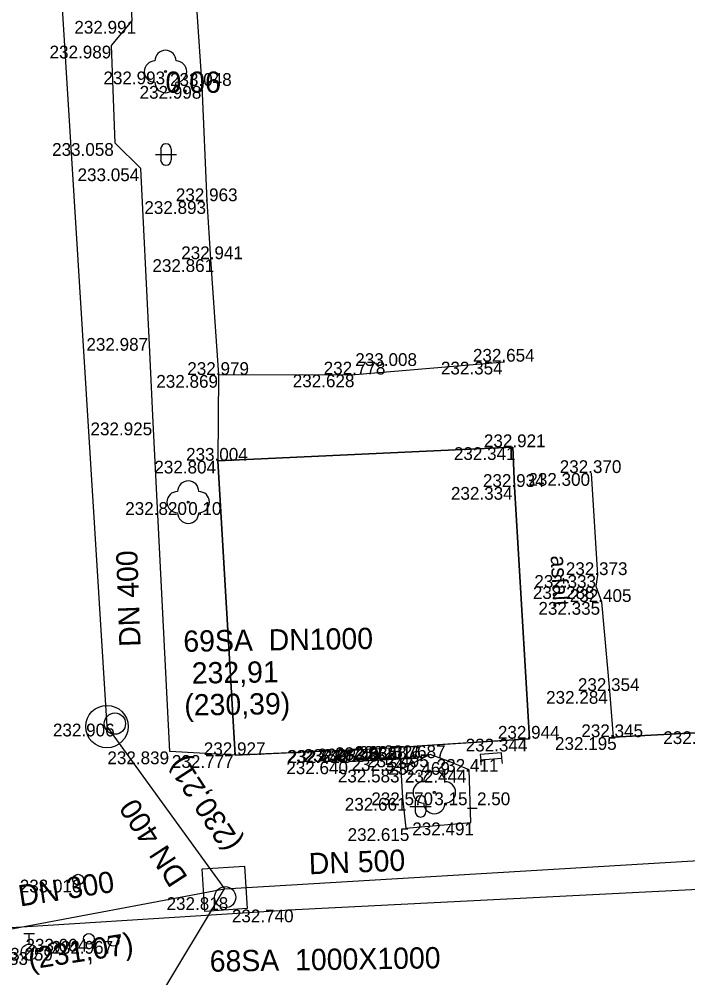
# Model space of a CAD drawing. Extents: x -599516 to -599132, y -1163668 to -1163119.
# Drawn here: x -599493.05 to -599477.33, y -1163377.96 to -1163355.43 of the extents above; entities that cross this region are included whole.
import ezdxf

# ---------------------------------------------------------------- set-up
doc = ezdxf.new("R2010")
doc.units = 0
for name, color, linetype in [('Bod-oznac1', 7, 'Continuous'), ('Bod-oznac2', 7, 'Continuous'), ('Bod-oznac3', 7, 'Continuous'), ('Bod-vyska1', 7, 'Continuous'), ('Bod-vyska2', 7, 'Continuous'), ('Bod-vyska3', 7, 'Continuous'), ('Z_cela-hrobu-dolni-linie', 7, 'Continuous'), ('Z_cela-hrobu-horni-linie', 7, 'Continuous'), ('Z_chodnik', 7, 'Continuous'), ('Z_kanalizace-destova', 7, 'Continuous'), ('Z_kanalizace-znacky-sachta', 7, 'Continuous'), ('Z_komunikace', 7, 'Continuous'), ('Z_komunikace-osa', 7, 'Continuous'), ('Z_kultury-znacky', 7, 'Continuous'), ('Z_nove-stromy-prumer-kmene', 7, 'Continuous'), ('Z_obvod-kmene-spodek-ve-vysce1_2m', 7, 'Continuous'), ('Z_podzemni-obrys-sachty', 7, 'Continuous'), ('Z_popis-budov-povrchu', 7, 'Continuous'), ('Z_stromy-kere', 7, 'Continuous'), ('Z_stromy-nove-vysazene', 7, 'Continuous'), ('Z_voda-znacky-hydrant', 7, 'Continuous'), ('Z_voda-znacky-soupe', 7, 'Continuous'), ('Z_znacky-ostatni-lavicka', 7, 'Continuous'), ('Z_zpevnene-plochy', 7, 'Continuous')]:
    doc.layers.add(name, color=color, linetype=linetype)

msp = doc.modelspace()

# ---------------------------------------------------------------- linework, layer by layer
at = {"layer": 'Bod-oznac1'}
for p, q in [((-599490.396, -1163355.473), (-599490.396, -1163355.473)), ((-599490.875, -1163356.055), (-599490.875, -1163356.055)), ((-599489.609, -1163356.663), (-599489.609, -1163356.663)), ((-599488.758, -1163357.001), (-599488.758, -1163357.001)), ((-599490.794, -1163358.344), (-599490.794, -1163358.344)), ((-599490.185, -1163358.938), (-599490.185, -1163358.938)), ((-599488.636, -1163359.709), (-599488.636, -1163359.709)), ((-599488.55, -1163361.072), (-599488.55, -1163361.072)), ((-599489.996, -1163362.923), (-599489.996, -1163362.923)), ((-599481.64, -1163363.48), (-599481.64, -1163363.48)), ((-599488.366, -1163363.792), (-599488.366, -1163363.792)), ((-599485.147, -1163363.781), (-599485.147, -1163363.781)), ((-599489.902, -1163364.909), (-599489.902, -1163364.909)), ((-599481.44, -1163365.489), (-599481.44, -1163365.489)), ((-599488.38, -1163365.807), (-599488.38, -1163365.807)), ((-599479.6, -1163366.096), (-599479.6, -1163366.096)), ((-599481.405, -1163366.423), (-599481.405, -1163366.423)), ((-599489.075, -1163366.78), (-599489.075, -1163366.78)), ((-599479.455, -1163368.493), (-599479.455, -1163368.493)), ((-599479.49, -1163368.755), (-599479.49, -1163368.755)), ((-599479.359, -1163369.125), (-599479.359, -1163369.125)), ((-599479.168, -1163371.217), (-599479.168, -1163371.217)), ((-599490.798, -1163371.984), (-599490.798, -1163371.984)), ((-599481.048, -1163372.338), (-599481.048, -1163372.338)), ((-599479.086, -1163372.301), (-599479.086, -1163372.301)), ((-599484.881, -1163372.584), (-599484.881, -1163372.584)), ((-599484.881, -1163372.585), (-599484.881, -1163372.585)), ((-599484.152, -1163372.54), (-599484.152, -1163372.54)), ((-599484.152, -1163372.542), (-599484.152, -1163372.542)), ((-599483.693, -1163372.512), (-599483.693, -1163372.512)), ((-599483.691, -1163372.512), (-599483.691, -1163372.512)), ((-599489.505, -1163372.637), (-599489.505, -1163372.637)), ((-599487.972, -1163372.723), (-599487.972, -1163372.723)), ((-599485.264, -1163372.607), (-599485.264, -1163372.607)), ((-599485.263, -1163372.607), (-599485.263, -1163372.607)), ((-599483.74, -1163372.794), (-599483.74, -1163372.794)), ((-599483.388, -1163372.709), (-599483.388, -1163372.709)), ((-599485.289, -1163372.871), (-599485.289, -1163372.871)), ((-599482.904, -1163372.886), (-599482.904, -1163372.886)), ((-599481.948, -1163372.815), (-599481.948, -1163372.815)), ((-599484.074, -1163373.065), (-599484.074, -1163373.065)), ((-599482.466, -1163373.068), (-599482.466, -1163373.068)), ((-599483.289, -1163373.6), (-599483.289, -1163373.6)), ((-599484.039, -1163373.729), (-599484.039, -1163373.729)), ((-599482.429, -1163374.306), (-599482.429, -1163374.306)), ((-599483.961, -1163374.441), (-599483.961, -1163374.441)), ((-599491.661, -1163375.649), (-599491.661, -1163375.649)), ((-599488.206, -1163376.062), (-599488.206, -1163376.062)), ((-599486.555, -1163376.352), (-599486.555, -1163376.352)), ((-599491.411, -1163377.04), (-599491.411, -1163377.04)), ((-599490.831, -1163377.09), (-599490.831, -1163377.09)), ((-599492.239, -1163377.252), (-599492.239, -1163377.252)), ((-599492.813, -1163377.352), (-599492.813, -1163377.352))]:
    msp.add_line(p, q, dxfattribs=at)
at = {"layer": 'Bod-oznac2'}
for p, q in [((-599488.758, -1163357.001), (-599488.758, -1163357.001)), ((-599488.636, -1163359.709), (-599488.636, -1163359.709)), ((-599488.55, -1163361.072), (-599488.55, -1163361.072)), ((-599481.64, -1163363.48), (-599481.64, -1163363.48)), ((-599488.366, -1163363.792), (-599488.366, -1163363.792)), ((-599485.147, -1163363.781), (-599485.147, -1163363.781)), ((-599481.44, -1163365.489), (-599481.44, -1163365.489)), ((-599488.38, -1163365.807), (-599488.38, -1163365.807)), ((-599479.6, -1163366.096), (-599479.6, -1163366.096)), ((-599481.405, -1163366.423), (-599481.405, -1163366.423)), ((-599479.455, -1163368.493), (-599479.455, -1163368.493)), ((-599479.359, -1163369.125), (-599479.359, -1163369.125)), ((-599479.168, -1163371.217), (-599479.168, -1163371.217)), ((-599481.048, -1163372.338), (-599481.048, -1163372.338)), ((-599479.086, -1163372.301), (-599479.086, -1163372.301)), ((-599487.972, -1163372.723), (-599487.972, -1163372.723)), ((-599483.74, -1163372.794), (-599483.74, -1163372.794)), ((-599485.289, -1163372.871), (-599485.289, -1163372.871))]:
    msp.add_line(p, q, dxfattribs=at)
at = {"layer": 'Bod-oznac3'}
msp.add_line((-599485.147, -1163363.781), (-599485.147, -1163363.781), dxfattribs=at)
at = {"layer": 'Z_cela-hrobu-dolni-linie'}
msp.add_line((-599487.972, -1163372.723), (-599488.38, -1163365.807), dxfattribs=at)
msp.add_lwpolyline([(-599489.004, -1163353.298), (-599488.758, -1163357.001), (-599488.636, -1163359.709), (-599488.55, -1163361.072), (-599488.366, -1163363.792)], dxfattribs=at)
at = {"layer": 'Z_cela-hrobu-horni-linie'}
msp.add_line((-599479.6, -1163366.096), (-599479.455, -1163368.493), dxfattribs=at)
for points in [[(-599489.004, -1163353.298), (-599488.758, -1163357.001), (-599488.636, -1163359.709), (-599488.55, -1163361.072), (-599488.366, -1163363.792), (-599485.147, -1163363.781), (-599485.147, -1163363.781), (-599481.64, -1163363.48)], [(-599484.152, -1163372.542), (-599484.152, -1163372.54), (-599481.048, -1163372.338), (-599481.405, -1163366.423), (-599481.44, -1163365.489), (-599488.38, -1163365.807)], [(-599488.38, -1163365.807), (-599487.972, -1163372.723), (-599484.881, -1163372.584), (-599484.881, -1163372.585), (-599484.152, -1163372.542)], [(-599479.086, -1163372.301), (-599476.413, -1163372.163), (-599476.413, -1163372.163), (-599473.687, -1163371.969), (-599473.687, -1163371.969), (-599471.002, -1163371.829), (-599471.002, -1163371.829), (-599468.212, -1163371.65), (-599468.212, -1163371.65), (-599466.846, -1163371.574), (-599466.846, -1163371.574), (-599461.29, -1163371.24), (-599461.384, -1163367.744)], [(-599479.359, -1163369.125), (-599479.168, -1163371.217), (-599479.086, -1163372.301)]]:
    msp.add_lwpolyline(points, dxfattribs=at)
at = {"layer": 'Z_chodnik'}
for points in [[(-599488.366, -1163363.792), (-599485.147, -1163363.781), (-599481.64, -1163363.48)], [(-599488.366, -1163363.792), (-599488.38, -1163365.807), (-599481.44, -1163365.489)]]:
    msp.add_lwpolyline(points, dxfattribs=at)
at = {"layer": 'Z_kanalizace-destova'}
for p, q in [((-599494.722, -1163312.287), (-599490.985, -1163372.054)), ((-599488.219, -1163375.862), (-599421.433, -1163371.876)), ((-599490.985, -1163372.054), (-599488.219, -1163375.862)), ((-599502.504, -1163378.542), (-599488.219, -1163375.862)), ((-599490.798, -1163380.14), (-599488.219, -1163375.862))]:
    msp.add_line(p, q, dxfattribs=at)
at = {"layer": 'Z_kanalizace-znacky-sachta'}
for centre in [(-599490.798, -1163371.984), (-599488.206, -1163376.062)]:
    msp.add_circle(centre, 0.25, dxfattribs=at)
at = {"layer": 'Z_komunikace'}
for points in [[(-599489.902, -1163364.909), (-599489.996, -1163362.923), (-599490.185, -1163358.938), (-599490.794, -1163358.344), (-599490.875, -1163356.055), (-599490.396, -1163355.473), (-599490.586, -1163351.474), (-599490.883, -1163347.19), (-599491.117, -1163346.799), (-599491.182, -1163345.761), (-599490.938, -1163344.776), (-599491.152, -1163341.79), (-599492.205, -1163340.898), (-599492.27, -1163339.868), (-599491.269, -1163338.743), (-599491.456, -1163334.806), (-599491.693, -1163331.006), (-599492.092, -1163330.613), (-599492.139, -1163328.983), (-599491.859, -1163328.546), (-599491.882, -1163327.381), (-599492.1, -1163323.823), (-599492.5, -1163319.448)], [(-599481.44, -1163365.489), (-599481.405, -1163366.423), (-599481.048, -1163372.338), (-599483.691, -1163372.512), (-599483.74, -1163372.794), (-599485.289, -1163372.871), (-599485.264, -1163372.607), (-599487.972, -1163372.723), (-599489.505, -1163372.637), (-599489.902, -1163364.909)], [(-599479.6, -1163366.096), (-599479.455, -1163368.493), (-599479.49, -1163368.755), (-599479.359, -1163369.125), (-599479.168, -1163371.217), (-599479.086, -1163372.301)], [(-599476.413, -1163372.163), (-599479.086, -1163372.301)], [(-599484.074, -1163373.065), (-599484.039, -1163373.729), (-599483.961, -1163374.441), (-599482.429, -1163374.306), (-599482.466, -1163373.068), (-599482.904, -1163372.886), (-599483.388, -1163372.709), (-599484.074, -1163373.065)]]:
    msp.add_lwpolyline(points, dxfattribs=at)
at = {"layer": 'Z_komunikace-osa'}
for points in [[(-599486.555, -1163376.352), (-599466.362, -1163375.334), (-599448.228, -1163374.387), (-599430.144, -1163373.279), (-599420.689, -1163372.612)], [(-599501.133, -1163377.406), (-599495.218, -1163376.901), (-599486.555, -1163376.352)]]:
    msp.add_lwpolyline(points, dxfattribs=at)
at = {"layer": 'Z_kultury-znacky'}
for p, q in [((-599489.847, -1163358.612), (-599489.347, -1163358.612)), ((-599489.722, -1163358.487), (-599489.722, -1163358.737)), ((-599489.472, -1163358.487), (-599489.472, -1163358.737)), ((-599483.861, -1163373.928), (-599483.361, -1163373.928)), ((-599483.736, -1163373.803), (-599483.736, -1163374.053)), ((-599483.486, -1163373.803), (-599483.486, -1163374.053))]:
    msp.add_line(p, q, dxfattribs=at)
for centre, start, end in [((-599489.598, -1163358.487), 0, 180), ((-599489.598, -1163358.737), 180, 0), ((-599483.611, -1163373.803), 0, 180), ((-599483.611, -1163374.053), 180, 0)]:
    msp.add_arc(centre, 0.125, start, end, dxfattribs=at)
at = {"layer": 'Z_podzemni-obrys-sachty'}
msp.add_line((-599488.684, -1163376.394), (-599488.75, -1163375.396), dxfattribs=at)
msp.add_lwpolyline([(-599488.75, -1163375.396), (-599487.754, -1163375.331), (-599487.688, -1163376.329), (-599488.684, -1163376.394)], dxfattribs=at)
msp.add_circle((-599490.985, -1163372.054), 0.5, dxfattribs=at)
at = {"layer": 'Z_stromy-kere'}
msp.add_circle((-599483.289, -1163373.6), 0.025, dxfattribs=at)
for centre, start, end in [((-599483.289, -1163373.35), 0, 180), ((-599483.539, -1163373.6), 90, 270), ((-599483.039, -1163373.6), 270, 90), ((-599483.289, -1163373.85), 180, 0)]:
    msp.add_arc(centre, 0.25, start, end, dxfattribs=at)
at = {"layer": 'Z_stromy-nove-vysazene'}
for centre in [(-599489.609, -1163356.663), (-599489.075, -1163366.78)]:
    msp.add_circle(centre, 0.025, dxfattribs=at)
for centre, start, end in [((-599489.609, -1163356.413), 0, 180), ((-599489.859, -1163356.663), 90, 270), ((-599489.359, -1163356.663), 270, 90), ((-599489.609, -1163356.913), 180, 0), ((-599489.075, -1163366.53), 0, 180), ((-599489.325, -1163366.78), 90, 270), ((-599488.825, -1163366.78), 270, 90), ((-599489.075, -1163367.03), 180, 0)]:
    msp.add_arc(centre, 0.25, start, end, dxfattribs=at)
at = {"layer": 'Z_voda-znacky-hydrant'}
for p, q in [((-599492.938, -1163376.914), (-599492.688, -1163376.914)), ((-599492.813, -1163377.164), (-599492.813, -1163376.914)), ((-599492.681, -1163377.22), (-599492.946, -1163377.485))]:
    msp.add_line(p, q, dxfattribs=at)
msp.add_circle((-599492.813, -1163377.352), 0.188, dxfattribs=at)
at = {"layer": 'Z_voda-znacky-soupe'}
for centre in [(-599491.661, -1163375.649), (-599491.411, -1163377.04), (-599490.831, -1163377.09), (-599492.239, -1163377.252)]:
    msp.add_circle(centre, 0.125, dxfattribs=at)
at = {"layer": 'Z_znacky-ostatni-lavicka'}
for p, q in [((-599481.688, -1163372.918), (-599481.699, -1163372.794)), ((-599482.186, -1163372.961), (-599482.197, -1163372.836))]:
    msp.add_line(p, q, dxfattribs=at)
msp.add_lwpolyline([(-599482.208, -1163372.712), (-599482.197, -1163372.836), (-599481.699, -1163372.794), (-599481.71, -1163372.669)], close=True, dxfattribs=at)
at = {"layer": 'Z_zpevnene-plochy'}
msp.add_lwpolyline([(-599485.263, -1163372.607), (-599485.289, -1163372.871), (-599483.74, -1163372.794), (-599483.693, -1163372.512)], dxfattribs=at)

# ---------------------------------------------------------------- texts
at = {"layer": 'Bod-vyska1'}
for s, p in [('232.991', (-599491.751, -1163355.773)), ('232.989', (-599492.334, -1163356.355)), ('232.993', (-599491.068, -1163356.963)), ('232.998', (-599490.217, -1163357.301)), ('233.058', (-599492.274, -1163358.644)), ('233.054', (-599491.676, -1163359.238)), ('232.893', (-599490.106, -1163360.009)), ('232.861', (-599489.916, -1163361.372)), ('232.987', (-599491.468, -1163363.223)), ('232.354', (-599483.133, -1163363.78)), ('232.869', (-599489.825, -1163364.092)), ('232.628', (-599486.617, -1163364.081)), ('232.925', (-599491.372, -1163365.209)), ('232.341', (-599482.829, -1163365.789)), ('232.804', (-599489.871, -1163366.107)), ('232.300', (-599481.078, -1163366.396)), ('232.334', (-599482.898, -1163366.723)), ('232.820', (-599490.555, -1163367.08)), ('232.333', (-599480.937, -1163368.793)), ('232.288', (-599480.972, -1163369.055)), ('232.335', (-599480.841, -1163369.425)), ('232.284', (-599480.661, -1163371.517)), ('232.906', (-599492.255, -1163372.284)), ('232.344', (-599482.552, -1163372.638)), ('232.195', (-599480.452, -1163372.601)), ('232.047', (-599477.906, -1163372.463)), ('232.853', (-599486.363, -1163372.885)), ('232.933', (-599486.351, -1163372.884)), ('232.953', (-599485.622, -1163372.84)), ('232.862', (-599485.622, -1163372.842)), ('232.687', (-599485.165, -1163372.812)), ('232.516', (-599485.057, -1163372.812)), ('232.839', (-599490.975, -1163372.937)), ('232.777', (-599489.459, -1163373.023)), ('232.740', (-599486.756, -1163372.907)), ('232.622', (-599486.734, -1163372.907)), ('232.547', (-599485.235, -1163373.094)), ('232.495', (-599484.869, -1163373.009)), ('232.411', (-599483.233, -1163373.115)), ('232.640', (-599486.769, -1163373.171)), ('232.469', (-599484.374, -1163373.186)), ('232.583', (-599485.556, -1163373.365)), ('232.444', (-599483.981, -1163373.368)), ('232.570', (-599484.77, -1163373.9)), ('232.661', (-599485.394, -1163374.029)), ('232.491', (-599483.807, -1163374.606)), ('232.615', (-599485.327, -1163374.741)), ('233.010', (-599493.035, -1163375.949)), ('232.818', (-599489.584, -1163376.362)), ('232.740', (-599488.048, -1163376.652)), ('233.004', (-599492.9, -1163377.34)), ('232.967', (-599492.292, -1163377.39)), ('233.059', (-599493.707, -1163377.552)), ('233.083', (-599494.293, -1163377.652))]:
    msp.add_text(s, height=0.3, dxfattribs=at).set_placement(p)
at = {"layer": 'Bod-vyska2'}
for s, p in [('233.048', (-599489.503, -1163357.001)), ('232.963', (-599489.365, -1163359.709)), ('232.941', (-599489.239, -1163361.072)), ('232.654', (-599482.381, -1163363.48)), ('232.979', (-599489.096, -1163363.792)), ('232.778', (-599485.89, -1163363.781)), ('232.921', (-599482.123, -1163365.489)), ('233.004', (-599489.125, -1163365.807)), ('232.370', (-599480.341, -1163366.096)), ('232.934', (-599482.146, -1163366.423)), ('232.373', (-599480.197, -1163368.493)), ('232.405', (-599480.104, -1163369.125)), ('232.354', (-599479.914, -1163371.217)), ('232.944', (-599481.794, -1163372.338)), ('232.345', (-599479.832, -1163372.301)), ('232.927', (-599488.708, -1163372.723)), ('232.740', (-599486.035, -1163372.871)), ('232.687', (-599484.476, -1163372.794))]:
    msp.add_text(s, height=0.3, dxfattribs=at).set_placement(p)
at = {"layer": 'Bod-vyska3'}
msp.add_text('233.008', height=0.3, dxfattribs=at).set_placement((-599485.147, -1163363.581))
at = {"layer": 'Z_kanalizace-destova'}
for s, rotation, p in [('DN 400', 92.0283, (-599490.193, -1163370.171)), ('69SA  DN1000', 0.8872, (-599489.186, -1163370.298)), (' 232,91', 0.8872, (-599489.174, -1163371.048)), ('(230,39)', 0.8872, (-599489.163, -1163371.797)), ('(230,21)', 122.9554, (-599487.812, -1163374.785)), ('DN 400', 122.9554, (-599489.071, -1163375.601)), ('DN 500', 2.1906, (-599486.23, -1163375.525)), ('DN 300', 8.8192, (-599493.026, -1163376.282)), ('(231,07)', 8.8192, (-599492.796, -1163377.764)), ('68SA  1000X1000', 0.8872, (-599488.566, -1163377.815))]:
    msp.add_text(s, height=0.5, rotation=rotation, dxfattribs=at).set_placement(p)
at = {"layer": 'Z_nove-stromy-prumer-kmene'}
for s, height, p in [('0.06', 0.5, (-599489.609, -1163357.163)), ('0.10', 0.3, (-599489.075, -1163367.08))]:
    msp.add_text(s, height=height, dxfattribs=at).set_placement(p)
at = {"layer": 'Z_obvod-kmene-spodek-ve-vysce1_2m'}
msp.add_text('3.15_2.50', height=0.3, dxfattribs=at).set_placement((-599483.289, -1163373.9))
at = {"layer": 'Z_popis-budov-povrchu'}
msp.add_text('asfalt', height=0.375, rotation=273.4503, dxfattribs=at).set_placement((-599480.557, -1163368.041))

doc.saveas('drawing.dxf')
